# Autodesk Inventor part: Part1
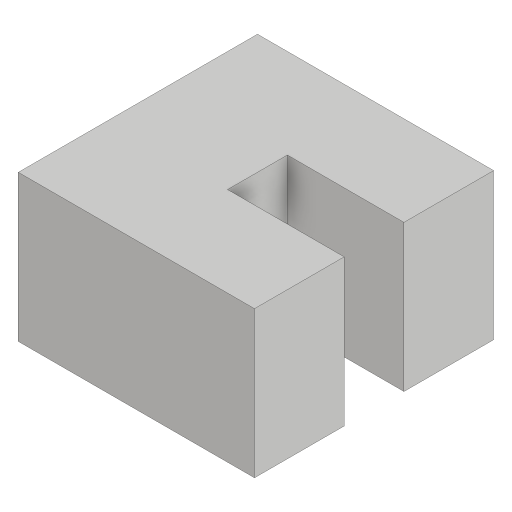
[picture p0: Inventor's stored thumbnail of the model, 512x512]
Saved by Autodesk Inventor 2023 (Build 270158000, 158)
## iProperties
Created: 2015-07
Part Number: Part1
Material: Generic
Document SubType Name: Modeling
Designer: Sandeep
Density: 1 g/cm^3
Appearance: Default
Author: Sandeep
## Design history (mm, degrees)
sketch "Sketch1"
  geometry: L1 (0, 0)-(-30, 0); L2 (-30, 0)-(-30, 40); L3 (-30, 40)-(0, 40); L4 (0, 40)-(0, 0)
  constraints: 8 end point, 2 parallel, 1 horizontal, 1 perpendicular
  dimensions: "d0" = 30 distance between parallel lines of L4 L2; "d1" = 40 distance of L1.end L2.end
extrude "Extrusion1" new body sketch "Sketch1" distance "d2" = 15; taper "d3" = 0 deg
sketch "Sketch2"
  geometry: L1 (0, 40)-(0, 0) reference; L2 (-15, 0)-(-15, 40) reference; L3 (0, 0)-(-15, 0) reference; L4 (-15, 15)-(0, 15); L5 (0, 15)-(0, 25); L6 (0, 25)-(-15, 25); L7 (-15, 25)-(-15, 15)
  constraints: 8 end point, 2 parallel, 2 point on line, 1 horizontal, 1 perpendicular
  dimensions: "d4" = 10 distance between parallel lines of L6 L4; "d5" = 15 distance between parallel lines of L3 L4
extrude "Extrusion2" cut sketch "Sketch2" distance "d6" = 10; taper "d7" = 0 deg
node "Direct Edit2"
body "Solid1"
feature "Size2" dims "d9" = 9.5
